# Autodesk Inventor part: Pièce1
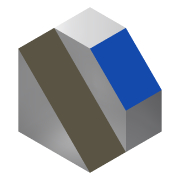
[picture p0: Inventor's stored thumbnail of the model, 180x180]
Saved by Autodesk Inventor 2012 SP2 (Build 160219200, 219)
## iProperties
Created: 2013-10
Part Number: Pièce1
Material: Alliage nickel-cuivre 400
Document SubType Name: Modeling
Designer: papa
Mass: 48.565 g
Surface Area: 21.2426 cm^2
Volume: 5.5 cm^3
Density: 8.83 g/cm^3
Author: papa
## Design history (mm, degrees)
sketch "Esquisse1"
  geometry: L1 (-10, 10)-(10, 10); L2 (10, 10)-(10, -10); L3 (10, -10)-(-10, -10); L4 (-10, -10)-(-10, 10); L5 (0, 0)-(15.698, 0); L6 (0, 0)-(0, 13.299)
  constraints: 12 end point, 3 perpendicular, 2 parallel, 1 horizontal, 2 other
  dimensions: "d0" = 20 distance of L1.start L1.end; "d1" = 20 distance of L3.end L1.start
extrude "Extrusion1" new body sketch "Esquisse1" distance "d2" = 20; taper "d3" = 0 deg
sketch "Esquisse2"
  geometry: L1 (20, 20)-(0, 20) reference; L2 (20, 0)-(20, 20) reference; L3 (0, 20)-(20, 0); L4 (20, 0)-(29.818, 11.442); L5 (29.818, 11.442)-(18.652, 26.601); L6 (18.652, 26.601)-(0, 20); 1 further point
  constraints: 8 end point
extrude "Extrusion2" cut sketch "Esquisse2" distance "d4" = 10; taper "d5" = 0 deg
chamfer "Chanfrein1" distance "d6" = 10; stored, may be unused: second distance "d7" = 2, angle "d8" = 45 deg
node "Solide1"
